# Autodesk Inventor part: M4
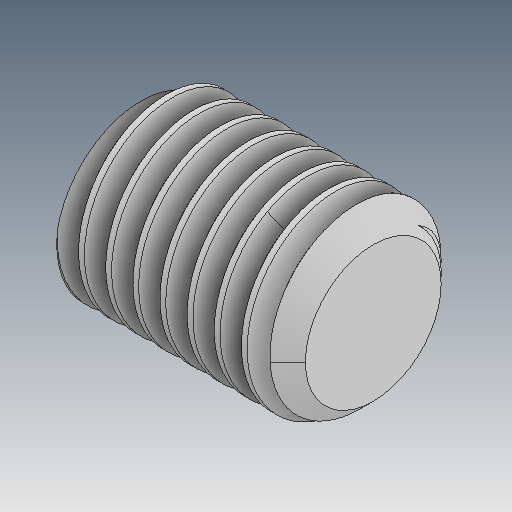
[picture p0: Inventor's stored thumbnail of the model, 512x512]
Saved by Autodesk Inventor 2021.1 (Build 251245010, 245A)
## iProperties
Created: 2019-04
Part Number: M4
Material: Ogólny
Document SubType Name: Modeling
Designer: user
Density: 1 g/cm^3
Appearance: Domyślna
Author: user
Revision Number: ÈÎºÎ
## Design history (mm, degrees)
feature "ÊäÈë1"
node "Bryła1"
